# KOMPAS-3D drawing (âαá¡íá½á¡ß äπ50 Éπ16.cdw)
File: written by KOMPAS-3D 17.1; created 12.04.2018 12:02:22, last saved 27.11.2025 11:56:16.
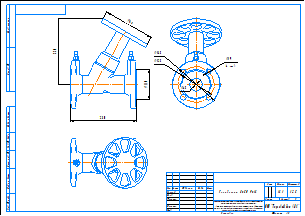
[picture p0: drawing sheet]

Sheet 1: A3, landscape

Title block, sheet 1: name: Гранбаланс Ду50 Ру16; material: Сталь 20  ГОСТ 1050-2013; mass: 16,1; sheets: 1; sheet format: A3; stored path: C:\Users\kka\KOMPAS_Work\!Trash\КМ125 КМ127 КМ225Ф Двухходовые клапана\КМ125Ф + PSL\KOMPAS 2D\Гранрег КМ125Ф Ду32 Ру16.cdw

Views: Спереди 1, Спереди, Проекционный вид 2, Проекционный вид 3
Referenced files in C:\Users\mipv\Desktop\КБЧ\Имеющиеся\: Гранбаланс Ду50 Ру16  серия 10.m3d
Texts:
  kka
  adl
  Рама для чертежей
  Лит-Масса-Масштаб
  Материал-Предприятие
  Масштаб
  Изм.
  Лист
  № докум.
  Подп.
  Дата
  Лит.
  Разраб.
  Пров.
  Т.контр.
  Листов
  Внимание! Данный продукт является объектом авторского права ООО «Торговый Дом АДЛ».
  Запрещается изменение, копирование, распространение
  (в том числе путем копирования на другие сайты и ресурсы в Интернете)
  или любое иное использование информации и объектов без предварительного
  согласия правообладателя (ООО «Торговый Дом АДЛ»).
  Н.контр.
  Утв.
  ООО "Торговый дом АДЛ"
  Изменение
  Номер документа
  Подпись
  Обозначение документа
  Наименование изделия
  Масса изделия по ГОСТ 2.109-73
  Порядковый номер листа
  Общее количество листов в документе
  Характер работы, выполненной лицом, подписавшим документ
  Наименование или индекс предприятия, выпускающего документ
  Инв. № подл.
  Подп. и дата
  Взам. инв. №
  Инв. № дубл.
  Инвентарный номер подлинника по ГОСТ 2.501-68
  Подпись принявшего подлинник в отдел технической документации
  Инвентарный номер подлинника, взамен которого выпущен данный подлинник
  Инвентарный номер дубликата по ГОСТ 2.502-68
  Подпись принявшего дубликат в отдел технической документации
  Справ. №
  Перв. примен.
  Обозначение документа, взамен или на основании которого выпущен данный документ
  Обозначение документа, в котором впервые записан данный документ
  Подпись лица, копировавшего чертеж
  Обозначение формата листа
  !Рама для чертежа
Dimensions and other numbers on the sheet: 230; 228; 180; 118; 165; 125; 45; 19; 4 отв.; 1:2,5; 1; 16,1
